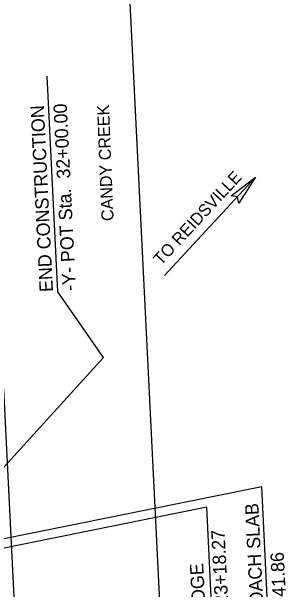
# Model space of a CAD drawing. Extents: x 1805231 to 1809482, y 908883 to 918297.
# Drawn here: x 1808278 to 1809007, y 914790 to 916301 of the extents above; entities that cross this region are included whole.
import ezdxf

# ---------------------------------------------------------------- set-up
doc = ezdxf.new("R2010")
doc.units = 0
for name, color, linetype in [('Prop DSN Text', 7, 'Continuous'), ('Prop Horizontal Alignment', 7, 'Continuous'), ('Prop Horizontal Alignment Station Label', 7, 'Continuous'), ('Prop Leader Line Medium', 7, 'Continuous'), ('Prop Shade Medium', 7, 'Continuous'), ('Prop Terminator CELL', 7, 'Continuous'), ('Scratch_Level_0', 7, 'Continuous')]:
    doc.layers.add(name, color=color, linetype=linetype)

msp = doc.modelspace()

# ---------------------------------------------------------------- linework, layer by layer
at = {"layer": 'Prop DSN Text'}
for p, q in [((1808931.8, 915059), (1807884.2, 914846.7)), ((1808959.4, 914503.3), (1808931.8, 915059)), ((1808787.6, 915006), (1807885.3, 914823.1)), ((1808809.7, 914561.4), (1808787.6, 915006))]:
    msp.add_line(p, q, dxfattribs=at)
at = {"layer": 'Prop Horizontal Alignment'}
msp.add_line((1807339.4, 914103.4), (1808518.2, 915396.8), dxfattribs=at)
at = {"layer": 'Prop Horizontal Alignment Station Label'}
for p, q in [((1808398.6, 915568.6), (1808370.6, 916132.7)), ((1808518.2, 915396.8), (1808398.6, 915568.6))]:
    msp.add_line(p, q, dxfattribs=at)
at = {"layer": 'Prop Leader Line Medium'}
msp.add_line((1808677.7, 915611), (1808915.3, 915868), dxfattribs=at)
at = {"layer": 'Prop Shade Medium'}
msp.add_lwpolyline([(1807282.7, 913769.8), (1808331.4, 913821.9), (1808257.3, 915314.8), (1807444, 915192.5), (1807212.6, 915181), (1807218.2, 915068.2)], close=True, dxfattribs=at)
at = {"layer": 'Prop Terminator CELL'}
msp.add_lwpolyline([(1808851.9, 915819.4), (1808915.3, 915868), (1808871.8, 915800.4), (1808868.4, 915817.3)], close=True, dxfattribs=at)
at = {"layer": 'Scratch_Level_0'}
msp.add_lwpolyline([(1807178.4, 913396.6), (1807021.1, 916565.5), (1808571, 916642.5), (1808728.3, 913473.6)], close=True, dxfattribs=at)

# ---------------------------------------------------------------- texts
at = {"layer": 'Prop DSN Text'}
for s, p in [('END APPROACH SLAB', (1808947.6, 914510.4)), ('-L- Sta.  23+18.27', (1808852.9, 914571.7)), ('-L- Sta.  23+41.86', (1809007.5, 914513.4)), ('END BRIDGE', (1808792.9, 914568.8))]:
    msp.add_text(s, height=35, rotation=92.8422, dxfattribs=at).set_placement(p)
at = {"layer": 'Prop Horizontal Alignment Station Label'}
for s, height, rotation, p in [('END CONSTRUCTION', 35, 92.8422, (1808386.1, 915569)), ('-Y- POT Sta.  32+00.00', 35, 92.8422, (1808446.1, 915571.9)), ('CANDY CREEK', 31.5, 92.3127, (1808544.5, 915754.3))]:
    msp.add_text(s, height=height, rotation=rotation, dxfattribs=at).set_placement(p)
at = {"layer": 'Prop Leader Line Medium'}
msp.add_text('TO REIDSVILLE', height=31.5, rotation=47.2558, dxfattribs=at).set_placement((1808668.6, 915636))

doc.saveas('drawing.dxf')
